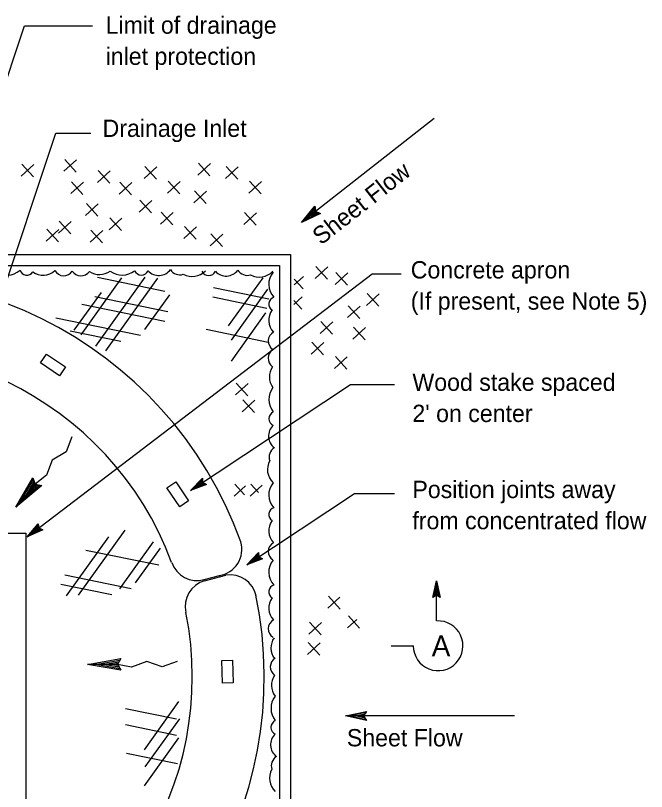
# Model space of a CAD drawing. Extents: x 6708945 to 6710368, y 1871409 to 1872338.
# Drawn here: x 6709235.1 to 6709453.9, y 1871634.3 to 1871903.3 of the extents above; entities that cross this region are included whole.
import ezdxf

# ---------------------------------------------------------------- set-up
doc = ezdxf.new("R2010")
doc.units = 0
for name, color, linetype in [('1 Control', 7, 'Continuous'), ('57 Undefined', 7, 'Continuous'), ('60 Nongeo Data', 7, 'Continuous'), ('62 As-Built Chng', 7, 'Continuous'), ('63 Undefined', 7, 'Continuous')]:
    doc.layers.add(name, color=color, linetype=linetype)

msp = doc.modelspace()

# ---------------------------------------------------------------- linework, layer by layer
at = {"layer": '1 Control'}
for p, q in [((6709338.91, 1871837.24), (6709338.91, 1871837.24)), ((6709340.89, 1871834.72), (6709340.89, 1871834.72)), ((6709334.23, 1871831.54), (6709334.23, 1871831.54))]:
    msp.add_line(p, q, dxfattribs=at)
msp.add_lwpolyline([(6709340.89, 1871834.72), (6709334.23, 1871831.54), (6709338.91, 1871837.24), (6709338.97, 1871836.75), (6709335.54, 1871832.58), (6709340.43, 1871834.89), (6709339.96, 1871835.07), (6709336.84, 1871833.59), (6709339.03, 1871836.25), (6709339.1, 1871835.76), (6709338.15, 1871834.61), (6709339.5, 1871835.25), (6709339.14, 1871835.39), (6709338.91, 1871837.24), (6709339.14, 1871835.39)], close=True, dxfattribs=at)
at = {"layer": '57 Undefined'}
for p, q in [((6709211.7, 1871820.34), (6709238.21, 1871899.71)), ((6709238.21, 1871899.71), (6709261.77, 1871899.71)), ((6709380.32, 1871867.62), (6709334.23, 1871831.54)), ((6709194.57, 1871699.25), (6709249.1, 1871862.48)), ((6709249.1, 1871862.48), (6709261.2, 1871862.48)), ((6709239.16, 1871722.53), (6709358.73, 1871813.77)), ((6709358.73, 1871813.77), (6709368.87, 1871813.77)), ((6709295.8, 1871738.64), (6709351.32, 1871775.38)), ((6709351.32, 1871775.38), (6709366.58, 1871775.38)), ((6709315.27, 1871712.85), (6709352.61, 1871737.56)), ((6709352.61, 1871737.56), (6709366.58, 1871737.56))]:
    msp.add_line(p, q, dxfattribs=at)
at = {"layer": '60 Nongeo Data'}
for p, q in [((6709299.9, 1871742.88), (6709299.9, 1871742.88)), ((6709301.31, 1871740.74), (6709301.31, 1871740.74)), ((6709295.8, 1871738.64), (6709295.8, 1871738.64)), ((6709242.97, 1871727.04), (6709242.97, 1871727.04)), ((6709244.52, 1871725.01), (6709244.52, 1871725.01)), ((6709239.16, 1871722.53), (6709239.16, 1871722.53)), ((6709319.37, 1871717.1), (6709319.37, 1871717.1)), ((6709320.79, 1871714.96), (6709320.79, 1871714.96)), ((6709315.27, 1871712.85), (6709315.27, 1871712.85)), ((6709300.57, 1871707.77), (6709305.8, 1871709.15)), ((6709300.66, 1871707.37), (6709308.03, 1871709.34))]:
    msp.add_line(p, q, dxfattribs=at)
for points in [[(6709301.31, 1871740.74), (6709295.8, 1871738.64), (6709299.9, 1871742.88), (6709299.92, 1871742.48), (6709296.91, 1871739.38), (6709300.96, 1871740.92), (6709300.6, 1871741.09), (6709298.01, 1871740.1), (6709299.93, 1871742.09), (6709299.95, 1871741.69), (6709299.12, 1871740.83), (6709300.24, 1871741.26), (6709299.96, 1871741.39), (6709299.9, 1871742.88), (6709299.96, 1871741.39)], [(6709244.52, 1871725.01), (6709239.16, 1871722.53), (6709242.97, 1871727.04), (6709243.01, 1871726.65), (6709240.22, 1871723.35), (6709244.15, 1871725.15), (6709243.78, 1871725.3), (6709241.27, 1871724.14), (6709243.05, 1871726.25), (6709243.1, 1871725.86), (6709242.33, 1871724.95), (6709243.42, 1871725.45), (6709243.13, 1871725.56), (6709242.97, 1871727.04), (6709243.13, 1871725.56)], [(6709320.79, 1871714.96), (6709315.27, 1871712.85), (6709319.37, 1871717.1), (6709319.39, 1871716.7), (6709316.39, 1871713.59), (6709320.43, 1871715.13), (6709320.07, 1871715.3), (6709317.49, 1871714.32), (6709319.41, 1871716.3), (6709319.42, 1871715.91), (6709318.59, 1871715.05), (6709319.71, 1871715.48), (6709319.44, 1871715.61), (6709319.37, 1871717.1), (6709319.44, 1871715.61)]]:
    msp.add_lwpolyline(points, close=True, dxfattribs=at)
for centre, radius, start, end in [((6709182.99, 1871674.08), 113.4, 20.4401, 11.3417), ((6709304.32, 1871718.32), 9.29, 279.1416, 15.6038), ((6709298.07, 1871716.72), 9.29, 198.9811, 285.6038), ((6709309.45, 1871700.15), 9.29, 12.0113, 98.7775), ((6709303.26, 1871698.45), 9.29, 106.2806, 192.8394)]:
    msp.add_arc(centre, radius, start, end, dxfattribs=at)
at = {"layer": '62 As-Built Chng'}
for p, q in [((6709237.03, 1871847.6), (6709241.43, 1871851.62)), ((6709237.28, 1871851.74), (6709241.3, 1871847.34)), ((6709251.91, 1871849.3), (6709256.3, 1871853.31)), ((6709252.16, 1871853.44), (6709256.17, 1871849.04)), ((6709279.96, 1871850.94), (6709283.98, 1871846.55)), ((6709298.27, 1871847.96), (6709302.67, 1871851.98)), ((6709298.52, 1871852.11), (6709302.54, 1871847.71)), ((6709308.15, 1871850.94), (6709312.17, 1871846.55)), ((6709263.51, 1871845.43), (6709267.91, 1871849.45)), ((6709263.76, 1871849.57), (6709267.78, 1871845.17)), ((6709279.71, 1871846.8), (6709284.11, 1871850.82)), ((6709307.9, 1871846.8), (6709312.3, 1871850.82)), ((6709254.23, 1871841.56), (6709258.62, 1871845.58)), ((6709254.48, 1871845.7), (6709258.5, 1871841.3)), ((6709271.26, 1871845.51), (6709275.28, 1871841.11)), ((6709287.83, 1871841.77), (6709292.23, 1871845.79)), ((6709288.08, 1871845.91), (6709292.1, 1871841.52)), ((6709316.02, 1871841.77), (6709320.42, 1871845.79)), ((6709316.27, 1871845.91), (6709320.29, 1871841.52)), ((6709271.01, 1871841.36), (6709275.41, 1871845.38)), ((6709296.95, 1871838.35), (6709301.35, 1871842.37)), ((6709297.2, 1871842.5), (6709301.22, 1871838.1)), ((6709259.41, 1871834.01), (6709263.81, 1871838.03)), ((6709259.66, 1871838.16), (6709263.68, 1871833.76)), ((6709277.97, 1871835.17), (6709282.37, 1871839.19)), ((6709278.23, 1871839.32), (6709282.24, 1871834.92)), ((6709285.35, 1871831), (6709289.75, 1871835.02)), ((6709285.6, 1871835.15), (6709289.62, 1871830.75)), ((6709314.24, 1871830.83), (6709318.64, 1871834.85)), ((6709314.49, 1871834.98), (6709318.51, 1871830.58)), ((6709267.53, 1871828.98), (6709271.93, 1871833)), ((6709267.78, 1871833.13), (6709271.8, 1871828.73)), ((6709249.96, 1871827.82), (6709254.36, 1871831.84)), ((6709250.21, 1871831.97), (6709254.23, 1871827.57)), ((6709293.47, 1871825.97), (6709297.87, 1871829.99)), ((6709293.72, 1871830.12), (6709297.74, 1871825.72)), ((6709245.71, 1871825.11), (6709250.11, 1871829.13)), ((6709245.96, 1871829.26), (6709249.98, 1871824.86)), ((6709260.96, 1871824.73), (6709265.36, 1871828.74)), ((6709261.21, 1871828.87), (6709265.23, 1871824.47)), ((6709302.64, 1871823.48), (6709307.04, 1871827.5)), ((6709302.89, 1871827.63), (6709306.91, 1871823.23)), ((6709338.99, 1871812.15), (6709343.39, 1871816.17)), ((6709339.24, 1871816.3), (6709343.26, 1871811.9)), ((6709345.9, 1871810.03), (6709350.3, 1871814.05)), ((6709346.16, 1871814.18), (6709350.17, 1871809.78)), ((6709331.73, 1871809.91), (6709334.95, 1871812.85)), ((6709331.77, 1871811.91), (6709334.82, 1871808.57)), ((6709331.59, 1871803.16), (6709334.48, 1871805.79)), ((6709356.83, 1871802.82), (6709361.22, 1871806.84)), ((6709357.08, 1871806.97), (6709361.1, 1871802.57)), ((6709331.62, 1871804.5), (6709334.35, 1871801.52)), ((6709350.25, 1871798.57), (6709354.65, 1871802.59)), ((6709350.5, 1871802.71), (6709354.52, 1871798.32)), ((6709340.77, 1871793.09), (6709345.17, 1871797.11)), ((6709341.02, 1871797.24), (6709345.04, 1871792.84)), ((6709352.04, 1871791.14), (6709356.43, 1871795.16)), ((6709352.29, 1871795.28), (6709356.31, 1871790.88)), ((6709337.64, 1871785.96), (6709342.03, 1871789.98)), ((6709337.89, 1871790.11), (6709341.9, 1871785.71)), ((6709345.76, 1871780.93), (6709350.15, 1871784.95)), ((6709346.01, 1871785.08), (6709350.03, 1871780.68)), ((6709311.4, 1871771.76), (6709315.8, 1871775.78)), ((6709311.65, 1871775.9), (6709315.67, 1871771.51)), ((6709313.72, 1871765.89), (6709318.12, 1871769.91)), ((6709313.97, 1871770.03), (6709317.99, 1871765.63)), ((6709311.2, 1871740.85), (6709314.56, 1871737.17)), ((6709316.72, 1871740.81), (6709319.38, 1871737.9)), ((6709310.95, 1871736.7), (6709314.82, 1871740.24)), ((6709316.47, 1871736.66), (6709320.69, 1871740.52)), ((6709379.84, 1871701.59), (6709381.12, 1871707.35)), ((6709380.18, 1871701.79), (6709381.12, 1871706.02)), ((6709381.12, 1871707.35), (6709381.12, 1871707.35)), ((6709381.12, 1871707.35), (6709382.4, 1871701.59)), ((6709381.12, 1871693.42), (6709381.12, 1871707.35)), ((6709381.13, 1871706.01), (6709382.06, 1871701.81)), ((6709380.52, 1871702.02), (6709381.12, 1871704.7)), ((6709380.86, 1871702.19), (6709381.12, 1871703.37)), ((6709381.12, 1871704.7), (6709381.72, 1871701.98)), ((6709381.12, 1871703.37), (6709381.38, 1871702.21)), ((6709343.37, 1871697.81), (6709347.62, 1871701.7)), ((6709343.62, 1871701.96), (6709347.64, 1871697.56)), ((6709381.12, 1871702.35), (6709379.84, 1871701.59)), ((6709379.84, 1871701.59), (6709379.84, 1871701.59)), ((6709382.4, 1871701.59), (6709381.12, 1871702.35)), ((6709382.4, 1871701.59), (6709382.4, 1871701.59)), ((6709350.53, 1871695.16), (6709354.39, 1871690.94)), ((6709336.79, 1871688.87), (6709341.19, 1871692.89)), ((6709337.04, 1871693.02), (6709341.06, 1871688.62)), ((6709350.28, 1871691.01), (6709353.51, 1871693.96)), ((6709336.32, 1871681.82), (6709340.72, 1871685.84)), ((6709336.57, 1871685.96), (6709340.59, 1871681.56)), ((6709365.33, 1871684.79), (6709373.06, 1871684.79)), ((6709408.11, 1871660.47), (6709349.57, 1871660.47)), ((6709349.57, 1871660.47), (6709349.57, 1871660.47)), ((6709356.77, 1871662.07), (6709356.77, 1871662.07)), ((6709356.77, 1871658.86), (6709356.77, 1871658.86))]:
    msp.add_line(p, q, dxfattribs=at)
for points in [[(6709036.13, 1871820.42), (6709330.46, 1871820.42), (6709330.46, 1871528.03), (6709036.13, 1871528.03)], [(6709040.24, 1871816.63), (6709326.68, 1871816.63), (6709326.68, 1871531.81), (6709040.24, 1871531.81)], [(6709243.81, 1871782.88), (6709245.87, 1871785.94), (6709252.46, 1871781.51), (6709250.4, 1871778.44)], [(6709287.62, 1871739.6), (6709290.69, 1871741.64), (6709295.1, 1871735.03), (6709292.03, 1871732.98)], [(6709126.63, 1871723.85), (6709238.71, 1871723.85), (6709238.71, 1871625.65), (6709126.63, 1871625.65)], [(6709306.67, 1871679.74), (6709310.35, 1871679.86), (6709310.61, 1871671.92), (6709306.92, 1871671.8)], [(6709356.77, 1871658.86), (6709349.57, 1871660.47), (6709356.77, 1871662.07), (6709356.52, 1871661.64), (6709351.24, 1871660.48), (6709356.52, 1871659.29), (6709356.26, 1871659.72), (6709352.89, 1871660.47), (6709356.26, 1871661.22), (6709356.01, 1871660.79), (6709354.55, 1871660.47), (6709356.01, 1871660.14), (6709355.81, 1871660.47), (6709356.77, 1871662.07), (6709355.81, 1871660.47)]]:
    msp.add_lwpolyline(points, close=True, dxfattribs=at)
for centre, radius, start, end in [((6709182.99, 1871674.08), 138.36, 19.738, 11.782), ((6709381.65, 1871684.8), 8.62, 180.1055, 93.4975)]:
    msp.add_arc(centre, radius, start, end, dxfattribs=at)
at = {"layer": '63 Undefined'}
for p, q in [((6709271.87, 1871812.32), (6709257.77, 1871792.64)), ((6709279.98, 1871812.58), (6709262.84, 1871788.67)), ((6709263.48, 1871812.6), (6709286.93, 1871807.79)), ((6709284.32, 1871812.22), (6709266.3, 1871787.08)), ((6709320.83, 1871812.42), (6709308.86, 1871795.73)), ((6709303.8, 1871809.04), (6709322.99, 1871805.1)), ((6709322.54, 1871808.48), (6709309.85, 1871790.78)), ((6709264.75, 1871807.31), (6709255.33, 1871794.17)), ((6709262.63, 1871805.84), (6709287.93, 1871800.65)), ((6709288.46, 1871806.53), (6709279.78, 1871794.42)), ((6709303.47, 1871805.74), (6709322.31, 1871801.88)), ((6709258.14, 1871803.26), (6709286.9, 1871797.36)), ((6709321.82, 1871800.21), (6709309.85, 1871783.52)), ((6709249.06, 1871798.55), (6709278.4, 1871792.53)), ((6709301.16, 1871794.53), (6709322.77, 1871790.09)), ((6709254, 1871794.04), (6709271.67, 1871790.41)), ((6709235.22, 1871732.88), (6709241.11, 1871743.01)), ((6709237, 1871734.99), (6709241.32, 1871742.42)), ((6709238.77, 1871737.08), (6709241.53, 1871741.83)), ((6709242.99, 1871740.6), (6709238.77, 1871737.08)), ((6709240.58, 1871739.22), (6709241.75, 1871741.23)), ((6709242.36, 1871740.71), (6709240.58, 1871739.22)), ((6709241.11, 1871743.01), (6709241.91, 1871740.79)), ((6709241.91, 1871740.79), (6709244.22, 1871740.38)), ((6709244.22, 1871740.38), (6709235.22, 1871732.88)), ((6709243.61, 1871740.49), (6709237, 1871734.99)), ((6709273.01, 1871724.94), (6709256.84, 1871702.38)), ((6709267.38, 1871722.63), (6709252.71, 1871702.17)), ((6709282.82, 1871720.88), (6709271.13, 1871704.56)), ((6709259.47, 1871718.01), (6709284.77, 1871712.82)), ((6709285.3, 1871718.7), (6709276.61, 1871706.59)), ((6709252.23, 1871709.42), (6709275.24, 1871704.7)), ((6709250.84, 1871706.2), (6709268.51, 1871702.58)), ((6709260.08, 1871678.3), (6709271.61, 1871680.39)), ((6709262.84, 1871678.31), (6709271.29, 1871679.85)), ((6709265.58, 1871678.33), (6709270.98, 1871679.3)), ((6709268.38, 1871678.34), (6709270.67, 1871678.75)), ((6709271.61, 1871680.39), (6709270.44, 1871678.35)), ((6709271.63, 1871676.32), (6709260.08, 1871678.3)), ((6709271.31, 1871676.85), (6709262.84, 1871678.31)), ((6709270.99, 1871677.4), (6709265.58, 1871678.33)), ((6709270.67, 1871677.94), (6709268.38, 1871678.34)), ((6709270.44, 1871678.35), (6709271.63, 1871676.32)), ((6709291.64, 1871665.48), (6709279.67, 1871648.79)), ((6709273.29, 1871663.09), (6709290.95, 1871659.46)), ((6709273.29, 1871657.48), (6709290.95, 1871653.86)), ((6709291.97, 1871659.54), (6709280, 1871642.85)), ((6709291.64, 1871652.94), (6709279.67, 1871636.25)), ((6709273.62, 1871647.59), (6709291.28, 1871643.96))]:
    msp.add_line(p, q, dxfattribs=at)
for points in [[(6709254.58, 1871757.28), (6709252.62, 1871752.01), (6709247.76, 1871749.2), (6709245.81, 1871743.94), (6709241.91, 1871740.79), (6709235.22, 1871732.88)], [(6709291.2, 1871679.39), (6709285.93, 1871677.47), (6709280.63, 1871679.34), (6709275.36, 1871677.42), (6709270.44, 1871678.35), (6709260.08, 1871678.3)]]:
    msp.add_lwpolyline(points, dxfattribs=at)
for centre, radius, start, end in [((6709232.19, 1871819.83), 6.54, 229.9986, 313.3536), ((6709239, 1871815.65), 2.4, 194.0578, 329.3233), ((6709244.61, 1871819.4), 6.1, 234.5002, 312.8354), ((6709251.79, 1871816.47), 3.41, 207.0211, 329.1913), ((6709257.78, 1871816.77), 3.68, 213.6905, 323.3403), ((6709264.23, 1871819.69), 6.2, 235.656, 306.6973), ((6709272.11, 1871820.34), 7, 233.3979, 307.9353), ((6709278.75, 1871815.88), 2.57, 204.5196, 335.4804), ((6709284.81, 1871818.17), 5, 222.1292, 323.705), ((6709292.12, 1871817.29), 3.88, 212.3474, 287.3796), ((6709296.32, 1871819.17), 6.36, 241.3634, 316.8458), ((6709302.09, 1871815.7), 2.57, 204.5196, 335.4804), ((6709308.15, 1871817.99), 5, 222.1292, 323.705), ((6709315.46, 1871817.11), 3.88, 212.3474, 287.3796), ((6709319.66, 1871818.99), 6.36, 241.3634, 316.8458), ((6709329.47, 1871810.1), 6.54, 139.9986, 223.3536), ((6709325.3, 1871803.28), 2.4, 104.0578, 239.3233), ((6709329.04, 1871797.68), 6.1, 144.5002, 222.8354), ((6709326.12, 1871790.49), 3.41, 117.0211, 239.1913), ((6709326.41, 1871784.5), 3.68, 123.6905, 233.3403), ((6709329.33, 1871778.05), 6.2, 145.656, 216.6973), ((6709329.99, 1871770.18), 7, 143.3979, 217.9353), ((6709325.53, 1871763.53), 2.57, 114.5196, 245.4804), ((6709327.82, 1871757.48), 5, 132.1292, 233.705), ((6709326.93, 1871750.17), 3.88, 122.3474, 197.3796), ((6709328.82, 1871745.96), 6.36, 151.3634, 226.8458), ((6709329.47, 1871737.11), 6.54, 139.9986, 223.3536), ((6709325.3, 1871730.3), 2.4, 104.0578, 239.3233), ((6709329.04, 1871724.69), 6.1, 144.5002, 222.8354), ((6709326.12, 1871717.51), 3.41, 117.0211, 239.1913), ((6709329.47, 1871710.32), 6.54, 139.9986, 223.3536), ((6709325.3, 1871703.51), 2.4, 104.0578, 239.3233), ((6709329.04, 1871697.9), 6.1, 144.5002, 222.8354), ((6709326.12, 1871690.72), 3.41, 117.0211, 239.1913), ((6709329.88, 1871684.07), 6.2, 145.656, 216.6973), ((6709327.14, 1871677.49), 3.68, 123.6905, 233.3403), ((6709330.06, 1871671.04), 6.2, 145.656, 216.6973), ((6709330.71, 1871663.16), 7, 143.3979, 217.9353), ((6709326.26, 1871656.52), 2.57, 114.5196, 245.4804), ((6709328.54, 1871650.46), 5, 132.1292, 233.705), ((6709327.66, 1871643.15), 3.88, 122.3474, 197.3796), ((6709329.54, 1871638.95), 6.36, 151.3634, 226.8458)]:
    msp.add_arc(centre, radius, start, end, dxfattribs=at)

# ---------------------------------------------------------------- texts
at = {"layer": '57 Undefined'}
for s, p in [('Limit of drainage', (6709266.35, 1871896.98)), ('inlet protection', (6709266.35, 1871886.18)), ('Drainage Inlet', (6709265.29, 1871861.21)), ('Concrete apron ', (6709372.16, 1871812.14)), ('(If present, see Note 5)', (6709372.16, 1871801.34)), ('Wood stake spaced ', (6709372.73, 1871773.18)), ("2' on center", (6709372.73, 1871762.38)), ('Position joints away ', (6709372.73, 1871736.01)), ('from concentrated flow', (6709372.73, 1871725.21))]:
    msp.add_text(s, height=6, dxfattribs=at).set_placement(p)
msp.add_text('Sheet Flow', height=6, rotation=38.0502, dxfattribs=at).set_placement((6709341.05, 1871823.52))
at = {"layer": '62 As-Built Chng'}
for s, height, p in [('A', 7.21, (6709379.45, 1871681.2)), ('Sheet Flow', 6, (6709350, 1871649.94))]:
    msp.add_text(s, height=height, dxfattribs=at).set_placement(p)

doc.saveas('drawing.dxf')
